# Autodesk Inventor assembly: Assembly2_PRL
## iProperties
Shininess: 64.0
Length Units: 11269
Angle Units: 11279
Time Units: 11290
Mass Units: 11283
Length Display Precision: 3
Angle Display Precision: 2
Compacted: True
Created: 2004-07
Part Number: Assembly2_PRL
Document SubType Name: Assembly
Designer: John Blackburn
Manufacturer: Standard
Standards Organization: Custom
Density: 0.0
Volumn: 0.0
Area: 0.0
PropertySet Name: Model Information
Control State: 0
Master: False
Checked Out: False
Author: John Blackburn
